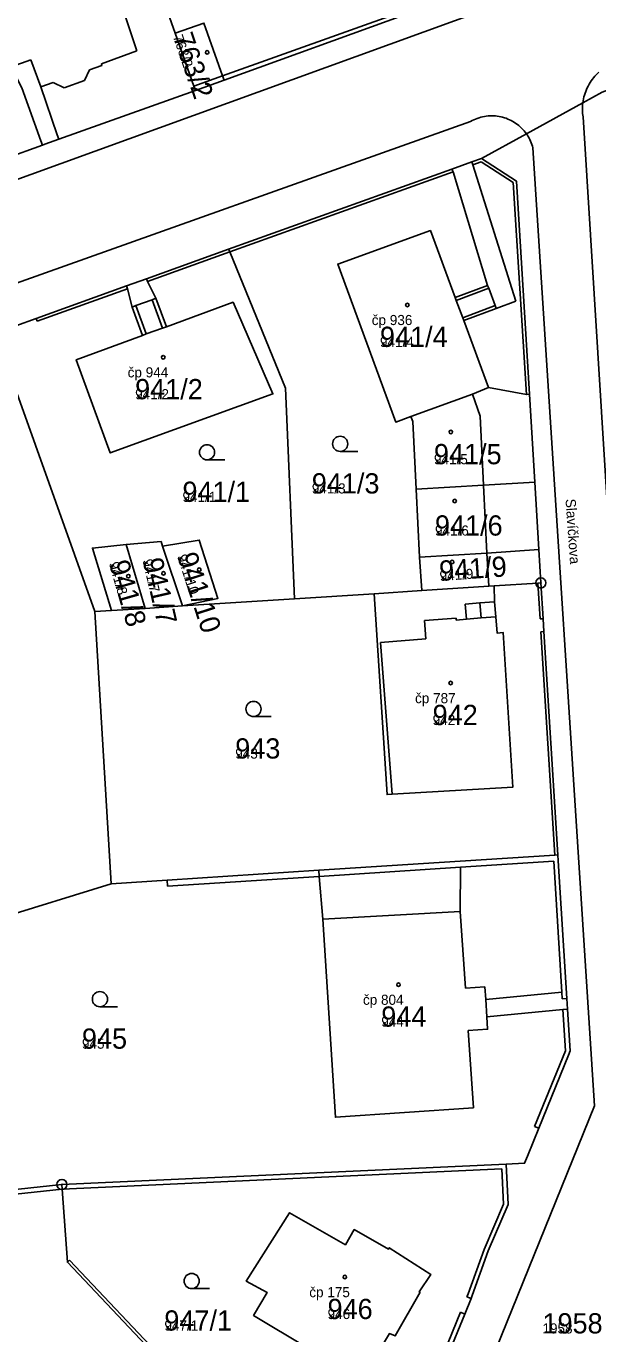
# Model space of a CAD drawing. Extents: x -763628 to -761565, y -976033 to -973833.
# Drawn here: x -762224.8 to -762168.3, y -974899.1 to -974769.9 of the extents above; entities that cross this region are included whole.
import ezdxf

# ---------------------------------------------------------------- set-up
doc = ezdxf.new("R2010")
doc.units = 0
for name, color, linetype in [('KN_cisla parcel 1000', 7, 'Continuous'), ('KN_cisla parcel 500', 7, 'Continuous'), ('KN_cisla popisna 500', 7, 'Continuous'), ('KN_hranice parcel', 7, 'Continuous'), ('KN_popisy', 7, 'Continuous'), ('KN_vnitrni kresba parcel', 7, 'Continuous'), ('KN_znacky bodu BP', 7, 'Continuous'), ('KN_znacky budov', 7, 'Continuous'), ('KN_znacky kultur', 7, 'Continuous')]:
    doc.layers.add(name, color=color, linetype=linetype)

msp = doc.modelspace()

# ---------------------------------------------------------------- linework, layer by layer
at = {"layer": 'KN_hranice parcel'}
for p, q in [((-762205.25, -974775.28), (-762187.22, -974768.75)), ((-762208.07, -974776.3), (-762205.25, -974775.28)), ((-762223.21, -974781.7), (-762226.88, -974783.01)), ((-762212.93, -974794.9), (-762204.81, -974791.99)), ((-762204.7, -974792.26), (-762204.81, -974791.99)), ((-762212.93, -974794.9), (-762214.9, -974795.61)), ((-762175.06, -974806.32), (-762174.53, -974815)), ((-762186.59, -974809.02), (-762186.78, -974808.51)), ((-762186.26, -974815.69), (-762186.59, -974809.02)), ((-762174.53, -974815), (-762174.13, -974821.67)), ((-762185.92, -974822.42), (-762186.26, -974815.69)), ((-762214.95, -974821.15), (-762211.48, -974820.87)), ((-762214.95, -974821.15), (-762213.05, -974827.47)), ((-762211.48, -974820.87), (-762211.33, -974821.31)), ((-762209.36, -974827.23), (-762211.33, -974821.31)), ((-762173.93, -974824.96), (-762174.13, -974821.67)), ((-762185.92, -974822.42), (-762185.71, -974825.72)), ((-762198.28, -974826.52), (-762209.36, -974827.23)), ((-762190.42, -974826.02), (-762198.28, -974826.52)), ((-762185.71, -974825.72), (-762190.42, -974826.02)), ((-762216.39, -974827.68), (-762218.02, -974827.78)), ((-762218.02, -974827.78), (-762216.42, -974854.68)), ((-762213.05, -974827.47), (-762216.39, -974827.68)), ((-762209.36, -974827.23), (-762213.05, -974827.47)), ((-762216.42, -974854.68), (-762241.72, -974862.51)), ((-762221.29, -974884.39), (-762177.35, -974882.38)), ((-762233.85, -974885.75), (-762221.29, -974884.39))]:
    msp.add_line(p, q, dxfattribs=at)
for points in [[(-762216.73, -974751.91), (-762218.43, -974752.51), (-762217.83, -974754.19), (-762225.46, -974757.08), (-762231.55, -974759.4), (-762228.19, -974769.07), (-762227.02, -974772.45), (-762226.88, -974772.4), (-762226.3, -974773.96), (-762225.26, -974776.04), (-762223.36, -974781.28), (-762223.21, -974781.7)], [(-762216.73, -974751.91), (-762215.81, -974754.52), (-762210.08, -974770.65)], [(-762210.08, -974770.65), (-762207.25, -974769.65), (-762205.4, -974774.87), (-762205.25, -974775.28)], [(-762210.08, -974770.65), (-762208.23, -974775.88), (-762208.07, -974776.3)], [(-762179.8, -974783.01), (-762175.36, -974780.57), (-762169.78, -974777.51), (-762167.85, -974776.46), (-762163.87, -974774.96)], [(-762223.21, -974781.7), (-762222.99, -974781.62), (-762221.6, -974781.12), (-762208.07, -974776.3)], [(-762204.81, -974791.99), (-762182.72, -974784.06), (-762180.77, -974783.36), (-762179.8, -974783.01)], [(-762179.8, -974783.01), (-762176.34, -974785.26), (-762175.06, -974806.32)], [(-762179.1, -974805.66), (-762181.56, -974799.03), (-762178.34, -974797.84), (-762178.45, -974797.56), (-762179.08, -974795.85), (-762179.19, -974795.56), (-762182.4, -974796.76), (-762184.85, -974790.15), (-762194.01, -974793.45), (-762188.28, -974809.06), (-762186.78, -974808.51)], [(-762198.28, -974826.52), (-762199.18, -974805.72), (-762204.7, -974792.26)], [(-762227.88, -974800.27), (-762223.84, -974798.82), (-762214.9, -974795.61)], [(-762214.9, -974795.61), (-762214.8, -974795.89), (-762214.36, -974797.7), (-762213.33, -974800.5), (-762219.88, -974802.9), (-762216.51, -974812.11), (-762200.42, -974806.29), (-762204.37, -974797.22), (-762210.96, -974799.64), (-762211.99, -974796.83), (-762212.83, -974795.18), (-762212.93, -974794.9)], [(-762218.02, -974827.78), (-762227.78, -974800.55), (-762227.88, -974800.27)], [(-762186.78, -974808.51), (-762180.7, -974806.32), (-762179.1, -974805.66)], [(-762179.1, -974805.66), (-762175.36, -974806.34), (-762175.06, -974806.32)], [(-762186.26, -974815.69), (-762179.6, -974815.3), (-762174.53, -974815)], [(-762216.39, -974827.68), (-762218.28, -974821.52), (-762214.95, -974821.15)], [(-762211.33, -974821.31), (-762207.71, -974820.73), (-762205.86, -974826.48), (-762209.36, -974827.23)], [(-762174.13, -974821.67), (-762179.28, -974822), (-762185.92, -974822.42)], [(-762190.42, -974826.02), (-762189.14, -974845.87), (-762188.64, -974845.84), (-762176.69, -974845.12), (-762177.64, -974829.87), (-762178.25, -974829.92), (-762178.38, -974828.3), (-762178.5, -974826.81), (-762178.56, -974825.26)], [(-762185.71, -974825.72), (-762179.07, -974825.29), (-762178.56, -974825.26)], [(-762178.56, -974825.26), (-762174.23, -974824.98), (-762173.93, -974824.96)], [(-762172.24, -974851.82), (-762173.63, -974829.76), (-762173.71, -974828.5), (-762173.93, -974824.96)], [(-762195.88, -974853.35), (-762181.92, -974852.45), (-762172.54, -974851.84), (-762172.24, -974851.82)], [(-762171.3, -974867.08), (-762171.36, -974866.03), (-762172.2, -974852.42), (-762172.24, -974851.82)], [(-762216.42, -974854.68), (-762210.89, -974854.32), (-762195.88, -974853.35)], [(-762195.88, -974853.35), (-762195.84, -974853.95), (-762195.48, -974858.19), (-762194.24, -974877.75), (-762180.6, -974876.81), (-762181.11, -974869.18), (-762179.19, -974869.05), (-762179.27, -974867.83), (-762171.74, -974867.11), (-762171.3, -974867.08)], [(-762177.35, -974882.38), (-762175.54, -974882.29), (-762175.25, -974881.58), (-762174.13, -974878.82), (-762171.2, -974871.61), (-762171.04, -974871.2), (-762171.3, -974867.08)], [(-762195.04, -974912.85), (-762192.37, -974910.04), (-762183.13, -974901.28), (-762181.46, -974897.19), (-762180.83, -974895.65), (-762180.71, -974895.35), (-762179.13, -974890.96), (-762177.16, -974886.37), (-762177.35, -974882.38)], [(-762221.29, -974884.39), (-762221.26, -974884.84), (-762220.75, -974892.07), (-762205.8, -974907.88)], [(-762185.87, -974895.04), (-762185.96, -974895), (-762184.81, -974893.28), (-762188.92, -974890.64), (-762189.01, -974890.79), (-762192.39, -974888.85), (-762193.25, -974890.35), (-762198.77, -974887.19), (-762203.06, -974893.94), (-762200.98, -974895.07), (-762202.34, -974897.33), (-762191.68, -974903.73), (-762188.9, -974899.12), (-762188.32, -974899.36), (-762185.87, -974895.04)]]:
    msp.add_lwpolyline(points, dxfattribs=at)
at = {"layer": 'KN_vnitrni kresba parcel'}
for p, q in [((-762215.75, -974766.72), (-762213.88, -974772.37)), ((-762179.09, -974768.19), (-762297.57, -974811.14)), ((-762205.4, -974774.87), (-762187.59, -974768.49)), ((-762213.88, -974772.37), (-762217.38, -974773.68)), ((-762224.37, -974773.26), (-762226.3, -974773.96)), ((-762223.37, -974775.94), (-762224.37, -974773.26)), ((-762217.33, -974773.82), (-762218.56, -974774.25)), ((-762217.38, -974773.68), (-762217.33, -974773.82)), ((-762219.06, -974775.3), (-762221.07, -974776.04)), ((-762218.56, -974774.25), (-762219.06, -974775.3)), ((-762208.23, -974775.88), (-762205.4, -974774.87)), ((-762222.14, -974775.51), (-762223.37, -974775.94)), ((-762221.75, -974780.7), (-762223.37, -974775.94)), ((-762221.07, -974776.04), (-762222.14, -974775.51)), ((-762169.76, -974778.91), (-762162.86, -974889.86)), ((-762229.02, -974796.5), (-762180.87, -974779.36)), ((-762221.6, -974781.12), (-762221.75, -974780.7)), ((-762168.63, -974876.62), (-762174.71, -974781.97)), ((-762182.61, -974784.34), (-762204.7, -974792.26)), ((-762182.72, -974784.06), (-762182.61, -974784.34)), ((-762179.19, -974795.56), (-762182.61, -974784.34)), ((-762180.77, -974783.36), (-762180.67, -974783.64)), ((-762180.67, -974783.64), (-762179.84, -974783.34)), ((-762180.67, -974783.64), (-762176.4, -974797.12)), ((-762179.84, -974783.34), (-762176.65, -974785.41)), ((-762175.36, -974806.34), (-762176.65, -974785.41)), ((-762204.7, -974792.26), (-762212.83, -974795.18)), ((-762223.74, -974799.1), (-762214.8, -974795.89)), ((-762182.3, -974797.04), (-762179.08, -974795.85)), ((-762213.98, -974797.56), (-762212.37, -974796.97)), ((-762212.37, -974796.97), (-762211.99, -974796.83)), ((-762212.37, -974796.97), (-762211.34, -974799.77)), ((-762182.4, -974796.76), (-762182.3, -974797.04)), ((-762182.3, -974797.04), (-762181.66, -974798.75)), ((-762176.4, -974797.12), (-762178.34, -974797.84)), ((-762214.36, -974797.7), (-762213.98, -974797.56)), ((-762213.98, -974797.56), (-762212.96, -974800.36)), ((-762181.66, -974798.75), (-762178.45, -974797.56)), ((-762223.84, -974798.82), (-762223.74, -974799.1)), ((-762212.96, -974800.36), (-762211.34, -974799.77)), ((-762211.34, -974799.77), (-762210.96, -974799.64)), ((-762181.66, -974798.75), (-762181.56, -974799.03)), ((-762212.96, -974800.36), (-762213.33, -974800.5)), ((-762180.7, -974806.32), (-762179.93, -974808.49)), ((-762179.93, -974808.49), (-762179.6, -974815.3)), ((-762179.6, -974815.3), (-762179.28, -974822)), ((-762179.28, -974822), (-762179.07, -974825.29)), ((-762174.01, -974828.52), (-762174.23, -974824.98)), ((-762179.96, -974826.93), (-762181.41, -974827.04)), ((-762178.5, -974826.81), (-762179.96, -974826.93)), ((-762179.96, -974826.93), (-762179.83, -974828.42)), ((-762181.28, -974828.53), (-762181.41, -974827.04)), ((-762185.44, -974828.68), (-762182.31, -974828.43)), ((-762185.3, -974830.48), (-762185.44, -974828.68)), ((-762182.31, -974828.43), (-762182.29, -974828.62)), ((-762182.29, -974828.62), (-762181.28, -974828.53)), ((-762181.28, -974828.53), (-762179.83, -974828.42)), ((-762179.83, -974828.42), (-762178.38, -974828.3)), ((-762173.71, -974828.5), (-762174.01, -974828.52)), ((-762189.8, -974830.84), (-762185.3, -974830.48)), ((-762188.64, -974845.84), (-762189.8, -974830.84)), ((-762173.93, -974829.78), (-762173.63, -974829.76)), ((-762172.54, -974851.84), (-762173.93, -974829.78)), ((-762181.88, -974853.04), (-762172.65, -974852.45)), ((-762172.65, -974852.45), (-762171.85, -974865.38)), ((-762210.85, -974854.92), (-762195.84, -974853.95)), ((-762195.84, -974853.95), (-762181.88, -974853.04)), ((-762181.88, -974853.04), (-762181.9, -974857.41)), ((-762210.89, -974854.32), (-762210.85, -974854.92)), ((-762195.48, -974858.19), (-762181.9, -974857.41)), ((-762181.9, -974857.41), (-762181.39, -974865)), ((-762181.39, -974865), (-762179.47, -974864.87)), ((-762179.38, -974866.1), (-762179.47, -974864.87)), ((-762171.85, -974865.38), (-762179.38, -974866.1)), ((-762171.81, -974866.06), (-762171.85, -974865.38)), ((-762179.27, -974867.83), (-762179.38, -974866.1)), ((-762171.81, -974866.06), (-762171.36, -974866.03)), ((-762171.74, -974867.11), (-762171.49, -974871.18)), ((-762174.55, -974878.66), (-762171.49, -974871.18)), ((-762179.35, -974903.08), (-762168.63, -974876.62)), ((-762174.13, -974878.82), (-762174.55, -974878.66)), ((-762177.78, -974882.85), (-762221.26, -974884.84)), ((-762177.78, -974882.85), (-762177.61, -974886.34)), ((-762221.26, -974884.84), (-762234.03, -974886.23)), ((-762177.61, -974886.34), (-762179.55, -974890.81)), ((-762179.55, -974890.81), (-762181.13, -974895.2)), ((-762220.53, -974891.86), (-762220.75, -974892.07)), ((-762205.58, -974907.67), (-762220.53, -974891.86)), ((-762181.13, -974895.2), (-762181.25, -974895.48)), ((-762181.25, -974895.48), (-762180.83, -974895.65)), ((-762183.53, -974901.06), (-762181.88, -974897.02)), ((-762181.88, -974897.02), (-762181.46, -974897.19))]:
    msp.add_line(p, q, dxfattribs=at)
for points in [[(-762168.18, -974774.49), (-762168.32, -974774.62), (-762168.46, -974774.76), (-762168.59, -974774.9), (-762168.71, -974775.05), (-762168.83, -974775.2), (-762168.95, -974775.36), (-762169.05, -974775.52), (-762169.15, -974775.69), (-762169.25, -974775.86), (-762169.34, -974776.03), (-762169.42, -974776.21), (-762169.49, -974776.39), (-762169.56, -974776.57), (-762169.61, -974776.75), (-762169.67, -974776.94), (-762169.71, -974777.13), (-762169.75, -974777.32), (-762169.78, -974777.51)], [(-762169.78, -974777.51), (-762169.8, -974777.69), (-762169.81, -974777.86), (-762169.82, -974778.04), (-762169.82, -974778.21), (-762169.81, -974778.39), (-762169.8, -974778.56), (-762169.78, -974778.74), (-762169.76, -974778.91)], [(-762180.87, -974779.36), (-762180.71, -974779.27), (-762180.55, -974779.19), (-762180.38, -974779.12), (-762180.21, -974779.06), (-762180.04, -974779), (-762179.86, -974778.95), (-762179.69, -974778.9), (-762179.51, -974778.87), (-762179.33, -974778.84), (-762179.15, -974778.82), (-762178.97, -974778.81), (-762178.78, -974778.8), (-762178.6, -974778.81), (-762178.42, -974778.82), (-762178.24, -974778.84), (-762178.06, -974778.87), (-762177.88, -974778.9), (-762177.71, -974778.95), (-762177.53, -974778.99), (-762177.36, -974779.05), (-762177.19, -974779.12), (-762177.02, -974779.19), (-762176.86, -974779.27), (-762176.7, -974779.36), (-762176.54, -974779.45), (-762176.39, -974779.55), (-762176.24, -974779.66), (-762176.1, -974779.77), (-762175.96, -974779.89), (-762175.83, -974780.02), (-762175.7, -974780.15), (-762175.58, -974780.28), (-762175.47, -974780.42), (-762175.36, -974780.57)], [(-762175.36, -974780.57), (-762175.26, -974780.71), (-762175.17, -974780.86), (-762175.09, -974781.01), (-762175.01, -974781.16), (-762174.94, -974781.32), (-762174.87, -974781.48), (-762174.81, -974781.64), (-762174.76, -974781.8), (-762174.71, -974781.97)]]:
    msp.add_lwpolyline(points, dxfattribs=at)
at = {"layer": 'KN_znacky bodu BP'}
for centre, radius in [((-762173.93, -974824.96), 0.5), ((-762173.93, -974824.96), 0.0303), ((-762221.29, -974884.39), 0.5), ((-762221.29, -974884.39), 0.0303)]:
    msp.add_circle(centre, radius, dxfattribs=at)
at = {"layer": 'KN_znacky budov'}
for centre in [(-762206.93, -974772.54), (-762187.13, -974797.49), (-762211.27, -974802.66), (-762182.83, -974810.04), (-762182.45, -974816.87), (-762182.7, -974822.89), (-762214.72, -974824.29), (-762211.24, -974824.01), (-762207.71, -974823.65), (-762182.85, -974834.85), (-762188, -974864.65), (-762193.31, -974893.54)]:
    msp.add_circle(centre, 0.175, dxfattribs=at)
at = {"layer": 'KN_znacky kultur'}
for p, q in [((-762193.77, -974811.97), (-762192.02, -974811.97)), ((-762206.94, -974812.8), (-762205.19, -974812.8)), ((-762202.34, -974838.16), (-762200.59, -974838.16)), ((-762217.53, -974866.83), (-762215.78, -974866.83)), ((-762208.46, -974894.68), (-762206.71, -974894.68))]:
    msp.add_line(p, q, dxfattribs=at)
for centre in [(-762206.94, -974812.05), (-762193.77, -974811.22), (-762202.34, -974837.41), (-762217.53, -974866.08), (-762208.46, -974893.93)]:
    msp.add_circle(centre, 0.75, dxfattribs=at)

# ---------------------------------------------------------------- texts
at = {"layer": 'KN_cisla parcel 1000'}
for s, rotation, p in [('763/2', 289, (-762210.33, -974770.98)), ('941/8', 286, (-762216.65, -974823.02)), ('941/7', 283, (-762213.32, -974822.72)), ('941/10', 288, (-762209.91, -974822.31)), ('941/9', 4, (-762183.91, -974824.77))]:
    msp.add_text(s, height=2, rotation=rotation, dxfattribs=at).set_placement(p)
for s, p in [('941/4', (-762189.84, -974801.64)), ('941/2', (-762214.05, -974806.81)), ('941/5', (-762184.5, -974813.23)), ('941/3', (-762196.58, -974816.12)), ('941/1', (-762209.37, -974816.95)), ('941/6', (-762184.4, -974820.28)), ('942', (-762184.63, -974839)), ('943', (-762204.15, -974842.31)), ('944', (-762189.71, -974868.8)), ('945', (-762219.31, -974870.98)), ('947/1', (-762211.16, -974898.83)), ('946', (-762195.02, -974897.69)), ('1958', (-762173.77, -974899.11))]:
    msp.add_text(s, height=2, dxfattribs=at).set_placement(p)
at = {"layer": 'KN_cisla parcel 500'}
for s, rotation, p in [('763/2', 289, (-762210.33, -974770.98)), ('941/8', 286, (-762216.65, -974823.02)), ('941/7', 283, (-762213.32, -974822.72)), ('941/10', 288, (-762209.91, -974822.31)), ('941/9', 4, (-762183.91, -974824.77))]:
    msp.add_text(s, height=1, rotation=rotation, dxfattribs=at).set_placement(p)
for s, p in [('941/4', (-762189.84, -974801.64)), ('941/2', (-762214.05, -974806.81)), ('941/5', (-762184.5, -974813.23)), ('941/3', (-762196.58, -974816.12)), ('941/1', (-762209.37, -974816.95)), ('941/6', (-762184.4, -974820.28)), ('942', (-762184.63, -974839)), ('943', (-762204.15, -974842.31)), ('944', (-762189.71, -974868.8)), ('945', (-762219.31, -974870.98)), ('946', (-762195.02, -974897.69)), ('947/1', (-762211.16, -974898.83)), ('1958', (-762173.77, -974899.11))]:
    msp.add_text(s, height=1, dxfattribs=at).set_placement(p)
at = {"layer": 'KN_cisla popisna 500'}
for s, p in [('čp 936', (-762190.65, -974799.48)), ('čp 944', (-762214.79, -974804.65)), ('čp 787', (-762186.37, -974836.84)), ('čp 804', (-762191.52, -974866.64)), ('čp 175', (-762196.83, -974895.53))]:
    msp.add_text(s, height=1, dxfattribs=at).set_placement(p)
at = {"layer": 'KN_popisy'}
msp.add_text('Slavíčkova', height=1, rotation=274, dxfattribs=at).set_placement((-762171.49, -974816.68))

doc.saveas('drawing.dxf')
